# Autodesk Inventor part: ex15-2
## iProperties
Created: 2006-03
Part Number: ex15-2
Document SubType Name: Modeling
Designer: Elise Moss
Author: Elise Moss
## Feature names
1. Extrusion1
2. Hole1
3. Shell1
4. Chamfer1
